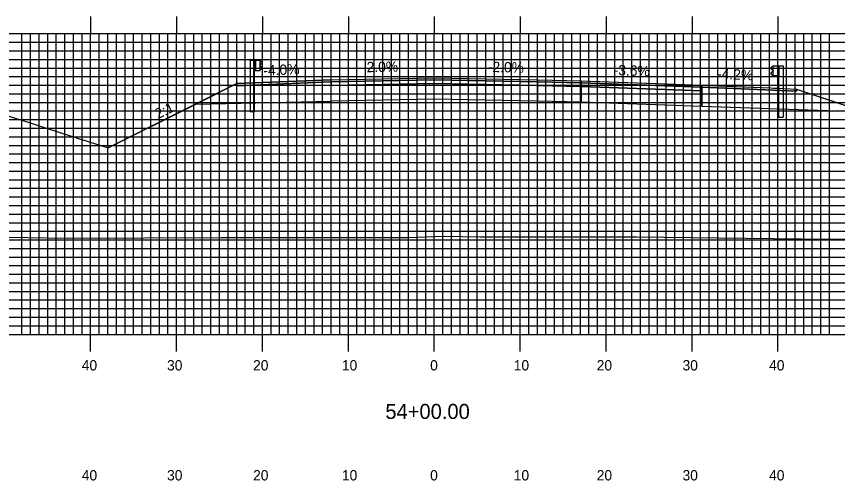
# Model space of a CAD drawing. Extents: x 1756282 to 1756625, y 442591 to 442811.
# Drawn here: x 1756398.9 to 1756494.5, y 442651.6 to 442705.7 of the extents above; entities that cross this region are included whole.
import ezdxf

# ---------------------------------------------------------------- set-up
doc = ezdxf.new("R2010")
doc.units = 0
for name, color, linetype in [('ANNOTATION', 7, 'Continuous'), ('D_Guardrail_Beam_Lt', 7, 'Continuous'), ('D_Guardrail_Beam_Rt', 7, 'Continuous'), ('D_Roadway_Centerline', 7, 'Continuous'), ('D_Roadway_Edge_Shoulder', 7, 'Continuous'), ('D_Roadway_Edge_TW', 7, 'Continuous'), ('D_Roadway_Pavement', 7, 'Continuous'), ('D_Roadway_SlopeLines', 7, 'Continuous'), ('D_Roadway_SubGrade', 7, 'Continuous'), ('H_V ANNOTATION', 7, 'Continuous'), ('MAJOR', 7, 'Continuous'), ('MINOR', 7, 'Continuous'), ('S_Roadway_Centerline', 7, 'Continuous')]:
    doc.layers.add(name, color=color, linetype=linetype)

msp = doc.modelspace()

# ---------------------------------------------------------------- linework, layer by layer
at = {"layer": 'D_Guardrail_Beam_Lt'}
for p, q in [((1756426.141, 442700.551), (1756426.141, 442694.551)), ((1756426.611, 442700.551), (1756426.141, 442700.551)), ((1756427.299, 442700.551), (1756426.611, 442700.551)), ((1756426.611, 442700.551), (1756426.611, 442699.385)), ((1756426.674, 442700.551), (1756426.674, 442699.385)), ((1756426.778, 442700.551), (1756426.778, 442699.385)), ((1756427.299, 442699.385), (1756427.299, 442700.551)), ((1756427.299, 442700.468), (1756427.373, 442700.453)), ((1756427.389, 442700.447), (1756427.532, 442700.347)), ((1756426.611, 442699.385), (1756427.299, 442699.385)), ((1756426.632, 442694.551), (1756426.632, 442699.385)), ((1756427.373, 442699.482), (1756427.299, 442699.468)), ((1756427.303, 442700.003), (1756427.303, 442699.933)), ((1756427.532, 442700.204), (1756427.337, 442700.067)), ((1756427.337, 442699.868), (1756427.532, 442699.732)), ((1756427.532, 442699.589), (1756427.389, 442699.489)), ((1756426.632, 442694.551), (1756426.141, 442694.551))]:
    msp.add_line(p, q, dxfattribs=at)
for centre, major_axis, start_param, end_param in [((1756427.365, 442700.413), (0.0417, 0), 0.959931, 1.376053), ((1756427.482, 442700.275), (0.0877, 0), 5.323254, 7.243116), ((1756427.382, 442700.003), (-0.0789, 0), 5.323254, 6.283185), ((1756427.382, 442699.933), (-0.0789, 0), 6.283185, 7.243116), ((1756427.365, 442699.523), (0.0417, 0), 4.907132, 5.323254), ((1756427.482, 442699.661), (0.0877, 0), 5.323254, 7.243116)]:
    msp.add_ellipse(centre, major_axis=major_axis, ratio=0.995501, start_param=start_param, end_param=end_param, dxfattribs=at)
at = {"layer": 'D_Guardrail_Beam_Rt'}
for p, q in [((1756486.914, 442699.822), (1756486.77, 442699.722)), ((1756486.77, 442699.579), (1756486.966, 442699.443)), ((1756487.004, 442699.843), (1756486.93, 442699.829)), ((1756486.999, 442699.378), (1756486.999, 442699.308)), ((1756487.004, 442699.926), (1756487.691, 442699.926)), ((1756487.004, 442698.76), (1756487.004, 442699.926)), ((1756487.525, 442699.926), (1756487.525, 442698.76)), ((1756487.629, 442699.926), (1756487.629, 442698.76)), ((1756487.691, 442699.926), (1756488.162, 442699.926)), ((1756487.691, 442699.926), (1756487.691, 442698.76)), ((1756488.162, 442699.926), (1756488.162, 442693.926)), ((1756486.966, 442699.244), (1756486.77, 442699.107)), ((1756486.77, 442698.964), (1756486.914, 442698.864)), ((1756486.93, 442698.858), (1756487.004, 442698.843)), ((1756487.691, 442698.76), (1756487.004, 442698.76)), ((1756487.671, 442693.926), (1756487.671, 442698.76)), ((1756487.671, 442693.926), (1756488.162, 442693.926))]:
    msp.add_line(p, q, dxfattribs=at)
for centre, major_axis, start_param, end_param in [((1756486.821, 442699.65), (-0.0877, 0), 5.323254, 7.243116), ((1756486.938, 442699.788), (-0.0417, 0), 4.907132, 5.323254), ((1756486.921, 442699.378), (0.0789, 0), 0, 0.959931), ((1756486.921, 442699.308), (0.0789, 0), 5.323254, 6.283185), ((1756486.821, 442699.036), (-0.0877, 0), 5.323254, 7.243116), ((1756486.938, 442698.898), (-0.0417, 0), 0.959931, 1.376053)]:
    msp.add_ellipse(centre, major_axis=major_axis, ratio=0.995501, start_param=start_param, end_param=end_param, dxfattribs=at)
at = {"layer": 'D_Roadway_Centerline'}
for points in [[(1756383.477, 442698.563), (1756400.395, 442693.335), (1756401.229, 442693.065), (1756401.356, 442693.024), (1756402.565, 442692.634), (1756402.577, 442692.63), (1756402.664, 442692.602), (1756402.71, 442692.587), (1756403.027, 442692.485), (1756403.175, 442692.437), (1756404.111, 442692.134), (1756404.35, 442692.057), (1756405.567, 442691.664), (1756405.604, 442691.652), (1756405.758, 442691.602), (1756406.016, 442691.519), (1756407.035, 442691.19), (1756407.38, 442691.079), (1756409.595, 442690.361)], [(1756409.595, 442690.361), (1756419.82, 442695.473), (1756424.57, 442697.848), (1756427.57, 442697.968), (1756435.57, 442698.288), (1756447.57, 442698.528), (1756459.57, 442698.288), (1756464.666, 442698.186), (1756471.187, 442697.948), (1756476.751, 442697.75), (1756477.654, 442697.718), (1756478.702, 442697.681), (1756482.647, 442697.515), (1756486.733, 442697.343), (1756487.05, 442697.33), (1756488.25, 442697.279), (1756489.745, 442697.216), (1756497.103, 442694.756)]]:
    msp.add_lwpolyline(points, dxfattribs=at)
at = {"layer": 'D_Roadway_Edge_Shoulder'}
for points in [[(1756435.57, 442698.288), (1756427.57, 442697.968), (1756427.57, 442697.968), (1756424.57, 442697.848), (1756424.57, 442697.598), (1756435.57, 442698.038)], [(1756478.702, 442697.681), (1756486.733, 442697.343), (1756486.733, 442697.343), (1756489.745, 442697.216), (1756489.745, 442696.966), (1756478.702, 442697.431)]]:
    msp.add_lwpolyline(points, close=True, dxfattribs=at)
at = {"layer": 'D_Roadway_Edge_TW'}
for points in [[(1756435.57, 442698.038), (1756435.57, 442698.288), (1756447.57, 442698.528), (1756459.57, 442698.288), (1756459.57, 442698.038), (1756447.57, 442698.278)], [(1756459.57, 442698.288), (1756464.666, 442698.186), (1756464.666, 442697.936), (1756459.57, 442698.038)], [(1756464.666, 442698.186), (1756478.702, 442697.681), (1756478.702, 442697.431), (1756464.666, 442697.936)]]:
    msp.add_lwpolyline(points, close=True, dxfattribs=at)
at = {"layer": 'D_Roadway_Pavement'}
for points in [[(1756435.57, 442697.621), (1756435.57, 442698.038), (1756447.57, 442698.278), (1756459.57, 442698.038), (1756459.57, 442697.621), (1756447.57, 442697.861)], [(1756459.57, 442698.038), (1756464.666, 442697.936), (1756464.666, 442697.519), (1756459.57, 442697.621)], [(1756464.666, 442697.936), (1756478.702, 442697.431), (1756478.702, 442697.014), (1756464.666, 442697.519)]]:
    msp.add_lwpolyline(points, close=True, dxfattribs=at)
for points in [[(1756435.57, 442698.038), (1756435.57, 442697.621)], [(1756478.702, 442697.431), (1756478.702, 442697.014)], [(1756478.702, 442697.431), (1756478.702, 442697.014)]]:
    msp.add_lwpolyline(points, dxfattribs=at)
at = {"layer": 'D_Roadway_SlopeLines'}
for points in [[(1756424.57, 442697.848), (1756409.595, 442690.361)], [(1756489.745, 442697.216), (1756540.465, 442680.261)]]:
    msp.add_lwpolyline(points, dxfattribs=at)
at = {"layer": 'D_Roadway_SubGrade'}
for points in [[(1756435.57, 442697.621), (1756435.57, 442698.038), (1756424.57, 442697.598), (1756424.57, 442697.848), (1756419.82, 442695.473), (1756435.57, 442695.788)], [(1756435.57, 442695.788), (1756435.57, 442697.621), (1756447.57, 442697.861), (1756459.57, 442697.621), (1756459.57, 442695.788), (1756447.57, 442696.028)], [(1756459.57, 442697.621), (1756464.666, 442697.519), (1756464.666, 442695.686), (1756459.57, 442695.788)], [(1756464.666, 442697.519), (1756478.702, 442697.014), (1756478.702, 442695.181), (1756464.666, 442695.686)], [(1756478.702, 442697.014), (1756478.702, 442697.431), (1756489.745, 442696.966), (1756489.745, 442697.216), (1756497.825, 442694.515), (1756478.702, 442695.181)]]:
    msp.add_lwpolyline(points, close=True, dxfattribs=at)
at = {"layer": 'MAJOR'}
for p, q in [((1756407.57, 442705.669), (1756407.57, 442703.665)), ((1756417.57, 442705.669), (1756417.57, 442703.665)), ((1756427.57, 442705.669), (1756427.57, 442703.665)), ((1756437.57, 442705.669), (1756437.57, 442703.665)), ((1756447.57, 442705.669), (1756447.57, 442703.665)), ((1756457.57, 442705.669), (1756457.57, 442703.665)), ((1756467.57, 442705.669), (1756467.57, 442703.665)), ((1756477.57, 442705.669), (1756477.57, 442703.665)), ((1756487.57, 442705.669), (1756487.57, 442703.665)), ((1756307.57, 442703.665), (1756587.57, 442703.665)), ((1756307.57, 442703.665), (1756587.57, 442703.665)), ((1756407.57, 442668.665), (1756407.57, 442703.665)), ((1756417.57, 442668.665), (1756417.57, 442703.665)), ((1756427.57, 442668.665), (1756427.57, 442703.665)), ((1756437.57, 442668.665), (1756437.57, 442703.665)), ((1756447.57, 442668.665), (1756447.57, 442703.665)), ((1756457.57, 442668.665), (1756457.57, 442703.665)), ((1756467.57, 442668.665), (1756467.57, 442703.665)), ((1756477.57, 442668.665), (1756477.57, 442703.665)), ((1756487.57, 442668.665), (1756487.57, 442703.665)), ((1756307.57, 442698.665), (1756587.57, 442698.665)), ((1756307.57, 442693.665), (1756587.57, 442693.665)), ((1756307.57, 442688.665), (1756587.57, 442688.665)), ((1756307.57, 442683.665), (1756587.57, 442683.665)), ((1756307.57, 442678.665), (1756587.57, 442678.665)), ((1756307.57, 442673.665), (1756587.57, 442673.665)), ((1756307.57, 442668.665), (1756587.57, 442668.665)), ((1756307.57, 442668.665), (1756587.57, 442668.665)), ((1756407.57, 442666.661), (1756407.57, 442668.665)), ((1756417.57, 442666.661), (1756417.57, 442668.665)), ((1756427.57, 442666.661), (1756427.57, 442668.665)), ((1756437.57, 442666.661), (1756437.57, 442668.665)), ((1756447.57, 442666.661), (1756447.57, 442668.665)), ((1756457.57, 442666.661), (1756457.57, 442668.665)), ((1756467.57, 442666.661), (1756467.57, 442668.665)), ((1756477.57, 442666.661), (1756477.57, 442668.665)), ((1756487.57, 442666.661), (1756487.57, 442668.665))]:
    msp.add_line(p, q, dxfattribs=at)
at = {"layer": 'MINOR'}
for p, q in [((1756399.57, 442668.665), (1756399.57, 442703.665)), ((1756400.57, 442668.665), (1756400.57, 442703.665)), ((1756401.57, 442668.665), (1756401.57, 442703.665)), ((1756402.57, 442668.665), (1756402.57, 442703.665)), ((1756403.57, 442668.665), (1756403.57, 442703.665)), ((1756404.57, 442668.665), (1756404.57, 442703.665)), ((1756405.57, 442668.665), (1756405.57, 442703.665)), ((1756406.57, 442668.665), (1756406.57, 442703.665)), ((1756408.57, 442668.665), (1756408.57, 442703.665)), ((1756409.57, 442668.665), (1756409.57, 442703.665)), ((1756410.57, 442668.665), (1756410.57, 442703.665)), ((1756411.57, 442668.665), (1756411.57, 442703.665)), ((1756412.57, 442668.665), (1756412.57, 442703.665)), ((1756413.57, 442668.665), (1756413.57, 442703.665)), ((1756414.57, 442668.665), (1756414.57, 442703.665)), ((1756415.57, 442668.665), (1756415.57, 442703.665)), ((1756416.57, 442668.665), (1756416.57, 442703.665)), ((1756418.57, 442668.665), (1756418.57, 442703.665)), ((1756419.57, 442668.665), (1756419.57, 442703.665)), ((1756420.57, 442668.665), (1756420.57, 442703.665)), ((1756421.57, 442668.665), (1756421.57, 442703.665)), ((1756422.57, 442668.665), (1756422.57, 442703.665)), ((1756423.57, 442668.665), (1756423.57, 442703.665)), ((1756424.57, 442668.665), (1756424.57, 442703.665)), ((1756425.57, 442668.665), (1756425.57, 442703.665)), ((1756426.57, 442668.665), (1756426.57, 442703.665)), ((1756428.57, 442668.665), (1756428.57, 442703.665)), ((1756429.57, 442668.665), (1756429.57, 442703.665)), ((1756430.57, 442668.665), (1756430.57, 442703.665)), ((1756431.57, 442668.665), (1756431.57, 442703.665)), ((1756432.57, 442668.665), (1756432.57, 442703.665)), ((1756433.57, 442668.665), (1756433.57, 442703.665)), ((1756434.57, 442668.665), (1756434.57, 442703.665)), ((1756435.57, 442668.665), (1756435.57, 442703.665)), ((1756436.57, 442668.665), (1756436.57, 442703.665)), ((1756438.57, 442668.665), (1756438.57, 442703.665)), ((1756439.57, 442668.665), (1756439.57, 442703.665)), ((1756440.57, 442668.665), (1756440.57, 442703.665)), ((1756441.57, 442668.665), (1756441.57, 442703.665)), ((1756442.57, 442668.665), (1756442.57, 442703.665)), ((1756443.57, 442668.665), (1756443.57, 442703.665)), ((1756444.57, 442668.665), (1756444.57, 442703.665)), ((1756445.57, 442668.665), (1756445.57, 442703.665)), ((1756446.57, 442668.665), (1756446.57, 442703.665)), ((1756448.57, 442668.665), (1756448.57, 442703.665)), ((1756449.57, 442668.665), (1756449.57, 442703.665)), ((1756450.57, 442668.665), (1756450.57, 442703.665)), ((1756451.57, 442668.665), (1756451.57, 442703.665)), ((1756452.57, 442668.665), (1756452.57, 442703.665)), ((1756453.57, 442668.665), (1756453.57, 442703.665)), ((1756454.57, 442668.665), (1756454.57, 442703.665)), ((1756455.57, 442668.665), (1756455.57, 442703.665)), ((1756456.57, 442668.665), (1756456.57, 442703.665)), ((1756458.57, 442668.665), (1756458.57, 442703.665)), ((1756459.57, 442668.665), (1756459.57, 442703.665)), ((1756460.57, 442668.665), (1756460.57, 442703.665)), ((1756461.57, 442668.665), (1756461.57, 442703.665)), ((1756462.57, 442668.665), (1756462.57, 442703.665)), ((1756463.57, 442668.665), (1756463.57, 442703.665)), ((1756464.57, 442668.665), (1756464.57, 442703.665)), ((1756465.57, 442668.665), (1756465.57, 442703.665)), ((1756466.57, 442668.665), (1756466.57, 442703.665)), ((1756468.57, 442668.665), (1756468.57, 442703.665)), ((1756469.57, 442668.665), (1756469.57, 442703.665)), ((1756470.57, 442668.665), (1756470.57, 442703.665)), ((1756471.57, 442668.665), (1756471.57, 442703.665)), ((1756472.57, 442668.665), (1756472.57, 442703.665)), ((1756473.57, 442668.665), (1756473.57, 442703.665)), ((1756474.57, 442668.665), (1756474.57, 442703.665)), ((1756475.57, 442668.665), (1756475.57, 442703.665)), ((1756476.57, 442668.665), (1756476.57, 442703.665)), ((1756478.57, 442668.665), (1756478.57, 442703.665)), ((1756479.57, 442668.665), (1756479.57, 442703.665)), ((1756480.57, 442668.665), (1756480.57, 442703.665)), ((1756481.57, 442668.665), (1756481.57, 442703.665)), ((1756482.57, 442668.665), (1756482.57, 442703.665)), ((1756483.57, 442668.665), (1756483.57, 442703.665)), ((1756484.57, 442668.665), (1756484.57, 442703.665)), ((1756485.57, 442668.665), (1756485.57, 442703.665)), ((1756486.57, 442668.665), (1756486.57, 442703.665)), ((1756488.57, 442668.665), (1756488.57, 442703.665)), ((1756489.57, 442668.665), (1756489.57, 442703.665)), ((1756490.57, 442668.665), (1756490.57, 442703.665)), ((1756491.57, 442668.665), (1756491.57, 442703.665)), ((1756492.57, 442668.665), (1756492.57, 442703.665)), ((1756493.57, 442668.665), (1756493.57, 442703.665)), ((1756307.57, 442702.665), (1756587.57, 442702.665)), ((1756307.57, 442701.665), (1756587.57, 442701.665)), ((1756307.57, 442700.665), (1756587.57, 442700.665)), ((1756307.57, 442699.665), (1756587.57, 442699.665)), ((1756307.57, 442697.665), (1756587.57, 442697.665)), ((1756307.57, 442696.665), (1756587.57, 442696.665)), ((1756307.57, 442695.665), (1756587.57, 442695.665)), ((1756307.57, 442694.665), (1756587.57, 442694.665)), ((1756307.57, 442692.665), (1756587.57, 442692.665)), ((1756307.57, 442691.665), (1756587.57, 442691.665)), ((1756307.57, 442690.665), (1756587.57, 442690.665)), ((1756307.57, 442689.665), (1756587.57, 442689.665)), ((1756307.57, 442687.665), (1756587.57, 442687.665)), ((1756307.57, 442686.665), (1756587.57, 442686.665)), ((1756307.57, 442685.665), (1756587.57, 442685.665)), ((1756307.57, 442684.665), (1756587.57, 442684.665)), ((1756307.57, 442682.665), (1756587.57, 442682.665)), ((1756307.57, 442681.665), (1756587.57, 442681.665)), ((1756307.57, 442680.665), (1756587.57, 442680.665)), ((1756307.57, 442679.665), (1756587.57, 442679.665)), ((1756307.57, 442677.665), (1756587.57, 442677.665)), ((1756307.57, 442676.665), (1756587.57, 442676.665)), ((1756307.57, 442675.665), (1756587.57, 442675.665)), ((1756307.57, 442674.665), (1756587.57, 442674.665)), ((1756307.57, 442672.665), (1756587.57, 442672.665)), ((1756307.57, 442671.665), (1756587.57, 442671.665)), ((1756307.57, 442670.665), (1756587.57, 442670.665)), ((1756307.57, 442669.665), (1756587.57, 442669.665))]:
    msp.add_line(p, q, dxfattribs=at)
at = {"layer": 'S_Roadway_Centerline'}
msp.add_lwpolyline([(1756398.082, 442679.978), (1756402.562, 442679.907), (1756404.868, 442679.863), (1756422.757, 442679.945), (1756444.498, 442679.934), (1756448.716, 442680.092), (1756452.91, 442680.014), (1756471.123, 442680.02), (1756493.511, 442679.73), (1756497.209, 442679.763), (1756504.866, 442679.615), (1756518.111, 442679.858), (1756535.573, 442680.207), (1756550.373, 442680.37), (1756550.691, 442680.399), (1756556.698, 442680.106), (1756579.053, 442679.057), (1756581.271, 442678.688), (1756582.237, 442677.831), (1756586.519, 442675.154), (1756587.57, 442675.154)], dxfattribs=at)

# ---------------------------------------------------------------- texts
at = {"layer": 'ANNOTATION'}
for s, rotation, p in [('-2.0%', 1.14576, (1756439.176, 442699.16)), ('-2.0%', 358.85424, (1756453.804, 442699.204)), ('-4.0%', 2.29061, (1756427.702, 442698.775)), ('-3.6%', 357.93576, (1756468.439, 442698.851)), ('-4.2%', 357.59013, (1756480.471, 442698.408)), ('2:1', 26.56505, (1756415.419, 442693.702))]:
    msp.add_text(s, height=1.2, rotation=rotation, dxfattribs=at).set_placement(p)
at = {"layer": 'D_Roadway_Centerline'}
for s, p in [('C', (1756447.565, 442698.528)), ('L', (1756447.57, 442698.521))]:
    msp.add_text(s, height=0.0146, dxfattribs=at).set_placement(p)
at = {"layer": 'H_V ANNOTATION'}
for s, height, p in [('40', 1.2, (1756406.542, 442664.465)), ('30', 1.2, (1756416.467, 442664.465)), ('20', 1.2, (1756426.478, 442664.465)), ('10', 1.2, (1756436.821, 442664.465)), ('0', 1.2, (1756447.088, 442664.465)), ('10', 1.2, (1756456.821, 442664.465)), ('20', 1.2, (1756466.478, 442664.465)), ('30', 1.2, (1756476.467, 442664.465)), ('40', 1.2, (1756486.542, 442664.465)), ('54+00.00', 1.75, (1756441.874, 442658.821)), ('40', 1.2, (1756406.542, 442651.665)), ('30', 1.2, (1756416.467, 442651.665)), ('20', 1.2, (1756426.478, 442651.665)), ('10', 1.2, (1756436.821, 442651.665)), ('0', 1.2, (1756447.088, 442651.665)), ('10', 1.2, (1756456.821, 442651.665)), ('20', 1.2, (1756466.478, 442651.665)), ('30', 1.2, (1756476.467, 442651.665)), ('40', 1.2, (1756486.542, 442651.665))]:
    msp.add_text(s, height=height, dxfattribs=at).set_placement(p)

doc.saveas('drawing.dxf')
